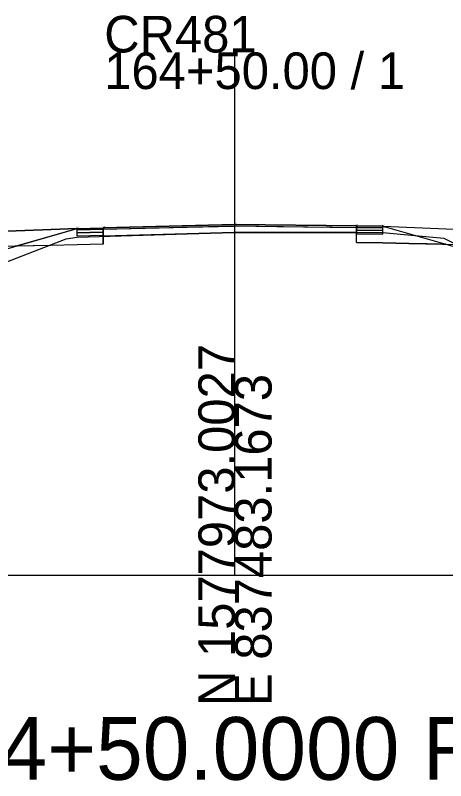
# Model space of a CAD drawing. Extents: x -26 to 303, y -16 to 6048.
# Drawn here: x 133.2 to 166.1, y 1984.3 to 2042.8 of the extents above; entities that cross this region are included whole.
import ezdxf

# ---------------------------------------------------------------- set-up
doc = ezdxf.new("R2010")
doc.units = 0
for name, color, linetype in [('ASPHALT_19MM1', 7, 'Continuous'), ('ASPHALT_9_5MM1', 7, 'Continuous'), ('Draft_XS_Text', 7, 'Continuous'), ('DTM_P_FINISHED_GRADE2', 7, 'Continuous'), ('DTM_X_GROUND', 7, 'Continuous'), ('TRANS_PAVED_SHOULDERS', 7, 'Continuous'), ('XS_CELL', 7, 'Continuous'), ('XS_M_SHAPES_EARTHWORK', 7, 'Continuous'), ('XS_P_ASPHALT', 7, 'Continuous'), ('XS_P_NULL_POINT', 7, 'Continuous'), ('XS_P_SHOULDER', 7, 'Continuous'), ('XS_P_SUBGRADE_GRANULAR', 7, 'Continuous'), ('XS_P_SUBGRADE_LEVELING', 7, 'Continuous'), ('XS_P_SUBGRADE_MILLING', 7, 'Continuous')]:
    doc.layers.add(name, color=color, linetype=linetype)

msp = doc.modelspace()

# ---------------------------------------------------------------- linework, layer by layer
at = {"layer": 'ASPHALT_19MM1'}
for points in [[(139.919, 2026.26), (139.919, 2025.989), (137.918, 2025.938), (137.918, 2026.209), (139.919, 2026.26)], [(159.298, 2026.392), (159.298, 2026.121), (161.298, 2026.095), (161.298, 2026.366), (159.298, 2026.392)]]:
    msp.add_lwpolyline(points, dxfattribs=at)
at = {"layer": 'ASPHALT_9_5MM1'}
for points in [[(139.919, 2026.593), (139.919, 2026.468), (137.918, 2026.417), (137.918, 2026.542), (139.919, 2026.593)], [(159.298, 2026.726), (159.298, 2026.601), (161.298, 2026.574), (161.298, 2026.699), (159.298, 2026.726)]]:
    msp.add_lwpolyline(points, dxfattribs=at)
at = {"layer": 'DTM_P_FINISHED_GRADE2'}
msp.add_lwpolyline([(103.19, 2016.726), (103.428, 2016.731), (131.918, 2026.302), (137.918, 2026.542), (139.919, 2026.593), (150, 2026.848), (159.298, 2026.726), (161.298, 2026.699), (167.381, 2026.456), (172.47, 2024.727), (173.481, 2024.391), (183.325, 2021.057), (193.989, 2017.587)], dxfattribs=at)
at = {"layer": 'DTM_X_GROUND'}
for points in [[(97.923, 2016.532), (101.4, 2016.662), (103.19, 2016.726), (103.346, 2016.729), (103.428, 2016.731), (129.878, 2024.228), (131.195, 2024.599), (137.918, 2026.542), (137.918, 2026.542), (139.919, 2026.593), (139.919, 2026.593), (150, 2026.848), (159.298, 2026.726), (159.298, 2026.726), (161.298, 2026.699), (161.298, 2026.699), (167.56, 2024.923), (168.261, 2024.728), (168.802, 2024.578), (180.91, 2021.154), (193.883, 2017.59), (193.989, 2017.587), (196.896, 2017.498), (203.123, 2017.307)], [(97.923, 2016.539), (106.131, 2016.831), (113.416, 2017.072), (115.411, 2017.161), (120.359, 2019.255), (137.083, 2025.752), (137.918, 2025.876), (146.352, 2026.125), (149.92, 2026.223), (153.19, 2026.22), (161.298, 2026.224), (163.765, 2025.996), (165.977, 2025.789), (179.536, 2019.058), (181.755, 2017.958), (203.123, 2017.309)]]:
    msp.add_lwpolyline(points, dxfattribs=at)
at = {"layer": 'TRANS_PAVED_SHOULDERS'}
for points in [[(139.919, 2026.468), (139.919, 2026.26), (137.918, 2026.209), (137.918, 2026.417), (139.919, 2026.468)], [(159.298, 2026.601), (159.298, 2026.392), (161.298, 2026.366), (161.298, 2026.574), (159.298, 2026.601)]]:
    msp.add_lwpolyline(points, dxfattribs=at)
at = {"layer": 'XS_CELL'}
for p, q in [((150, 2000), (150, 2040)), ((0, 2000), (150, 2000)), ((150, 2000), (300, 2000))]:
    msp.add_line(p, q, dxfattribs=at)
at = {"layer": 'XS_M_SHAPES_EARTHWORK'}
msp.add_lwpolyline([(133.196, 2025.177), (137.918, 2026.542), (139.919, 2026.593), (150, 2026.848), (159.298, 2026.726), (161.298, 2026.699), (166.118, 2025.332), (163.298, 2025.389), (161.298, 2025.429), (159.298, 2025.455), (159.298, 2026.121), (159.298, 2026.223), (153.19, 2026.22), (150, 2026.223), (149.92, 2026.223), (146.352, 2026.125), (139.919, 2025.935), (139.919, 2025.322), (137.918, 2025.272), (135.919, 2025.232)], close=True, dxfattribs=at)
at = {"layer": 'XS_P_ASPHALT'}
msp.add_lwpolyline([(139.919, 2026.593), (139.919, 2026.468), (139.919, 2026.468), (150, 2026.723), (159.298, 2026.601), (159.298, 2026.601), (159.298, 2026.726), (159.298, 2026.726), (159.298, 2026.726), (150, 2026.848), (139.919, 2026.593), (139.919, 2026.593), (139.919, 2026.593)], dxfattribs=at)
at = {"layer": 'XS_P_SHOULDER'}
for points in [[(137.918, 2026.542), (131.919, 2026.302)], [(161.298, 2026.699), (167.381, 2026.456)]]:
    msp.add_lwpolyline(points, dxfattribs=at)
at = {"layer": 'XS_P_SUBGRADE_GRANULAR'}
for points in [[(139.919, 2025.322), (139.919, 2026.593)], [(159.298, 2025.455), (159.298, 2026.726)], [(137.918, 2025.272), (135.919, 2025.232), (128.246, 2025.078)], [(139.919, 2025.322), (137.918, 2025.272)], [(159.298, 2025.455), (161.298, 2025.429)], [(161.298, 2025.429), (163.298, 2025.389), (171.048, 2025.234)]]:
    msp.add_lwpolyline(points, dxfattribs=at)
at = {"layer": 'XS_P_SUBGRADE_LEVELING'}
msp.add_lwpolyline([(159.298, 2026.601), (159.298, 2026.601), (159.298, 2026.601), (159.298, 2026.223), (159.298, 2026.223), (153.19, 2026.22), (153.19, 2026.22), (150, 2026.223), (150, 2026.223), (149.92, 2026.223), (146.352, 2026.125), (146.352, 2026.125), (139.919, 2025.935), (139.919, 2025.935), (139.919, 2026.468), (139.919, 2026.468), (139.919, 2026.468), (146.352, 2026.63), (146.352, 2026.63), (149.92, 2026.721), (150, 2026.723), (150, 2026.723), (153.19, 2026.681), (153.19, 2026.681), (159.298, 2026.601)], dxfattribs=at)
at = {"layer": 'XS_P_SUBGRADE_MILLING'}
msp.add_lwpolyline([(139.919, 2025.935), (139.919, 2025.935), (146.352, 2026.125), (146.352, 2026.125), (149.92, 2026.223), (150, 2026.223), (150, 2026.223), (153.19, 2026.22), (153.19, 2026.22), (159.298, 2026.223), (159.298, 2026.223)], dxfattribs=at)
msp.add_lwpolyline([(139.919, 2025.935), (139.919, 2025.935), (146.352, 2026.125), (146.352, 2026.125), (149.92, 2026.223), (150, 2026.223), (150, 2026.223), (153.19, 2026.22), (153.19, 2026.22), (159.298, 2026.223), (159.298, 2026.223)], dxfattribs=at)

# ---------------------------------------------------------------- texts
at = {"layer": 'Draft_XS_Text'}
msp.add_text('Sta. 164+50.0000 R1', height=4.8, dxfattribs=at).set_placement((111.716, 1984.35))
at = {"layer": 'XS_CELL'}
for s, p in [('CR481', (140, 2040)), ('164+50.00 / 1', (140, 2037.2))]:
    msp.add_text(s, height=2.8, dxfattribs=at).set_placement(p)
for s, p in [('N 1577973.0027', (150, 1990)), ('E 837483.1673', (152.8, 1990))]:
    msp.add_text(s, height=2.8, rotation=90, dxfattribs=at).set_placement(p)
at = {"layer": 'XS_P_NULL_POINT'}
for p in [(149.922, 2026.728), (159.22, 2026.606), (161.22, 2026.579), (137.84, 2026.422), (139.84, 2026.473)]:
    msp.add_text('X', height=0.24, dxfattribs=at).set_placement(p)

doc.saveas('drawing.dxf')
